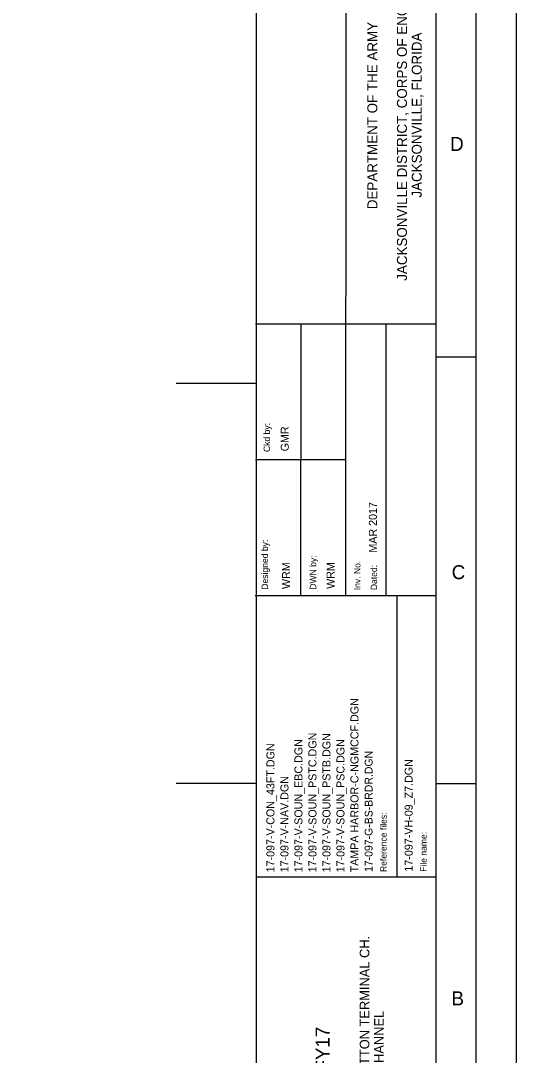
# Model space of a CAD drawing. Extents: x 515010 to 519411, y 1296833 to 1300233.
# Drawn here: x 518791 to 519410, y 1297660 to 1298953 of the extents above; entities that cross this region are included whole.
import ezdxf

# ---------------------------------------------------------------- set-up
doc = ezdxf.new("R2010")
doc.units = 0
for name, color, linetype in [('G-ANNO-NPLT', 7, 'Continuous'), ('G-ANNO-TEXT-DRWG', 7, 'Continuous'), ('G-ANNO-TEXT-PROJ', 7, 'Continuous'), ('G-ANNO-TEXT-TTLB', 7, 'Continuous'), ('G-ANNO-TTLB', 7, 'Continuous'), ('V-TOPO-COOR-STAT', 7, 'Continuous')]:
    doc.layers.add(name, color=color, linetype=linetype)

msp = doc.modelspace()

# ---------------------------------------------------------------- linework, layer by layer
at = {"layer": 'G-ANNO-NPLT'}
msp.add_lwpolyline([(515010.4, 1300233), (519410.4, 1300233), (519410.4, 1296833), (515010.4, 1296833)], close=True, dxfattribs=at)
at = {"layer": 'G-ANNO-TTLB'}
for p, q in [((519085.4, 1300133), (519085.4, 1296933)), ((519197.3, 1298235.1), (519197.9, 1299094.7)), ((519084.6, 1298574.8), (519310.4, 1298574.8)), ((519141.3, 1298235.2), (519141.6, 1298574.8)), ((519247.5, 1298574.8), (519247.5, 1298235.1)), ((519360.4, 1298532.9), (519310.4, 1298532.9)), ((519084.6, 1298405), (519197.4, 1298405)), ((519084.2, 1298235.1), (519310.4, 1298235.1)), ((519261.1, 1298235.1), (519261.1, 1297883.7)), ((519360.4, 1297999.6), (519310.4, 1297999.6)), ((519085.4, 1297883.7), (519310.4, 1297883.7))]:
    msp.add_line(p, q, dxfattribs=at)
for points in [[(515060.4, 1296883), (519360.4, 1296883), (519360.4, 1300183), (515060.4, 1300183)], [(519310.4, 1300133), (515185.4, 1300133), (515185.4, 1296933), (519310.4, 1296933)]]:
    msp.add_lwpolyline(points, close=True, dxfattribs=at)
at = {"layer": 'V-TOPO-COOR-STAT'}
for p, q in [((519085.4, 1298500), (518985.4, 1298500)), ((519085.4, 1298000), (518985.4, 1298000))]:
    msp.add_line(p, q, dxfattribs=at)

# ---------------------------------------------------------------- texts
at = {"layer": 'G-ANNO-TEXT-DRWG'}
for s, height, p in [('GMR', 10, (519126.1, 1298415.3)), ('WRM', 10, (519127.7, 1298243.2)), ('WRM', 10, (519183.3, 1298243.4)), ('TAMPA HARBOR-C-NGMCCF.DGN', 10, (519213.2, 1297889.1)), ('17-097-V-SOUN_EBC.DGN', 10, (519143.2, 1297889.1)), ('17-097-V-SOUN_PSTC.DGN', 10, (519160.7, 1297889.1)), ('17-097-V-SOUN_PSTB.DGN', 10, (519178.2, 1297889.1)), ('17-097-V-SOUN_PSC.DGN', 10, (519195.7, 1297889.1)), ('17-097-V-CON_43FT.DGN', 10, (519108.2, 1297889.1)), ('17-097-VH-09_Z7.DGN', 10, (519280.9, 1297890.1)), ('17-097-V-NAV.DGN', 10, (519125.7, 1297889.1)), ('STA. 15+00 PORT SUTTON CH. THRU STA. 3+00 PORT SUTTON TERMINAL CH.', 12, (519226.8, 1297206.1)), ('AND STA. 0+00 THRU STA. 2+00 EAST BAY CHANNEL', 12, (519244.8, 1297307.6))]:
    msp.add_text(s, height=height, rotation=90, dxfattribs=at).set_placement(p)
at = {"layer": 'G-ANNO-TEXT-PROJ'}
for s, height, p in [('MAR 2017', 10, (519236.2, 1298288.7)), ('17-097-G-BS-BRDR.DGN', 9.8, (519230.8, 1297889.5)), ('HYDROGRAPHIC EXAM SURVEY FY17', 17.5, (519177.2, 1297267))]:
    msp.add_text(s, height=height, rotation=90, dxfattribs=at).set_placement(p)
at = {"layer": 'G-ANNO-TEXT-TTLB'}
for s, height, p in [('JACKSONVILLE DISTRICT, CORPS OF ENGINEERS', 12.5, (519273.8, 1298628.5)), ('DEPARTMENT OF THE ARMY', 12.5, (519236.8, 1298717.9)), ('JACKSONVILLE, FLORIDA', 12.5, (519292.3, 1298732.4)), ('Ckd by:', 8, (519102.7, 1298414.4)), ('Designed by:', 8, (519100.2, 1298242.4)), ('DWN by:', 8, (519160.4, 1298242.4)), ('Inv. No.', 8, (519215.7, 1298241.7)), ('Dated:', 8, (519236.5, 1298241.8)), ('Reference files:', 8, (519248.5, 1297889.6)), ('File name:', 8, (519298.5, 1297889.8))]:
    msp.add_text(s, height=height, rotation=90, dxfattribs=at).set_placement(p)
at = {"layer": 'G-ANNO-TTLB'}
for s, p in [('D', (519327.8, 1298790.7)), ('C', (519329.7, 1298255.5)), ('B', (519329.5, 1297722.9))]:
    msp.add_text(s, height=17.5, dxfattribs=at).set_placement(p)

doc.saveas('drawing.dxf')
